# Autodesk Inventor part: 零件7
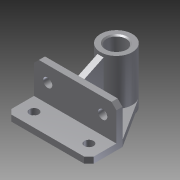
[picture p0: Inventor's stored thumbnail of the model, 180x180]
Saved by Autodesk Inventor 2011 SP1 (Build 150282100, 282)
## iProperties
Created: 2014-02
Part Number: 零件7
Document SubType Name: Modeling
Designer: yn
Density: 1 g/cm^3
Author: yn
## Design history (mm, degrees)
sketch "草图1"
  geometry: C1 r 16 at (0, 0); C2 r 26 at (0, 0); 1 further point
  constraints: 2 centre point, 2 coincident
  dimensions: "d0" = 32 diameter of C1; "d1" = 52 diameter of C2
extrude "拉伸1" new body sketch "草图1" distance "d2" = 90; taper "d3" = 0 deg
node "工作平面1"
sketch "草图2"
  geometry: L1 (-67.5, -90)-(67.5, -90); L2 (-59.5, -112.5)-(59.5, -112.5); L3 (-67.5, -57.5)-(67.5, -57.5); L4 (-67.5, -66.444)-(67.5, -66.444); L5 (-67.5, -57.5)-(-21.923, 13.979); L6 (67.5, -57.5)-(21.923, 13.979); L7 (-67.5, -112.5)-(-67.5, -57.5); L8 (67.5, -104.5)-(67.5, -57.5); L9 (-67.5, -104.5)-(-59.5, -112.5); L10 (67.5, -104.5)-(59.5, -112.5); C1 r 16 at (0, 0) reference; A1 r 26 centre (0, 0) between (-21.923, 13.979) and (21.923, 13.979) reference; 1 further point
  constraints: 20 end point, 3 parallel, 2 perpendicular, 2 point on circle, 2 tangent, 1 horizontal, 1 point on line
  dimensions: "d5" = 90 distance from line of L1 point (0, 0); "d6" = 135 distance of L1.start L1.end; "d7" = 22.5 distance between parallel lines of L2 L1; "d8" = 32.5 distance between parallel lines of L1 L3; "d9" = 8 distance of L7.start L9.start; "d10" = 8 distance of L2.start L7.start; "d12" = 55 distance of L3.start L7.start
extrude "拉伸2" join sketch "草图2" distance "d13" = 10; taper "d14" = 0 deg
sketch "草图3"
  geometry: L1 (-67.5, -104.5)-(-67.5, -57.5) reference; L2 (67.5, -57.5)-(67.5, -104.5) reference; L3 (67.5, -57.5)-(-67.5, -57.5); L4 (67.5, -67.5)-(-67.5, -67.5)
  constraints: 4 end point, 2 perpendicular, 2 point on line
  dimensions: "d15" = 10 distance between parallel lines of L3 L4
extrude "拉伸3" join sketch "草图3" distance "d16" = 55; taper "d17" = 0 deg
sketch "草图4"
  geometry: L1 (135, 55)-(0, 55) reference; L2 (0, 0)-(0, 55) reference; L3 (135, 0)-(135, 55) reference; L4 (135, 47)-(127, 55); L5 (8, 55)-(0, 47); 1 further point
  constraints: 4 end point, 4 point on line, 1 perpendicular
  dimensions: "d18" = 8 distance of L1.start L4.end; "d19" = 8 distance of L1.start L4.start; "d20" = 8 distance of L1.end L5.start
extrude "拉伸4" cut sketch "草图4" distance "d21" = 10; taper "d22" = 0 deg
sketch "草图5"
  geometry: L1 (-57.5, 70)-(-26, 85); L2 (-26, 85)-(-26, 15); 1 further point
  constraints: 4 end point
feature "加强筋1" sketch "草图5" dims "d24" = 1, "d25" = 10, "d26" = 0
chamfer "倒角1" distance "d27" = 2; stored, may be unused: second distance "d28" = 2, angle "d29" = 45 deg
hole "Hole1" diameter "d32" = 15; stored, may be unused: countersink angle "d36" = 90 deg, drill point angle "d38" = 118 deg; dims "d30" = 22.5, "d31" = 30, "d33" = 6, "d34" = 4, "d35" = 2, "d37" = 8
mirror "镜像1"
hole "Hole2" diameter "d41" = 15; stored, may be unused: countersink angle "d45" = 90 deg, drill point angle "d47" = 118 deg; dims "d39" = 22.5, "d40" = 22.5, "d42" = 6, "d43" = 4, "d44" = 2, "d46" = 8
mirror "镜像2"
node "实体1"
node "投影回路1"
other parameters: "d4" = -5
